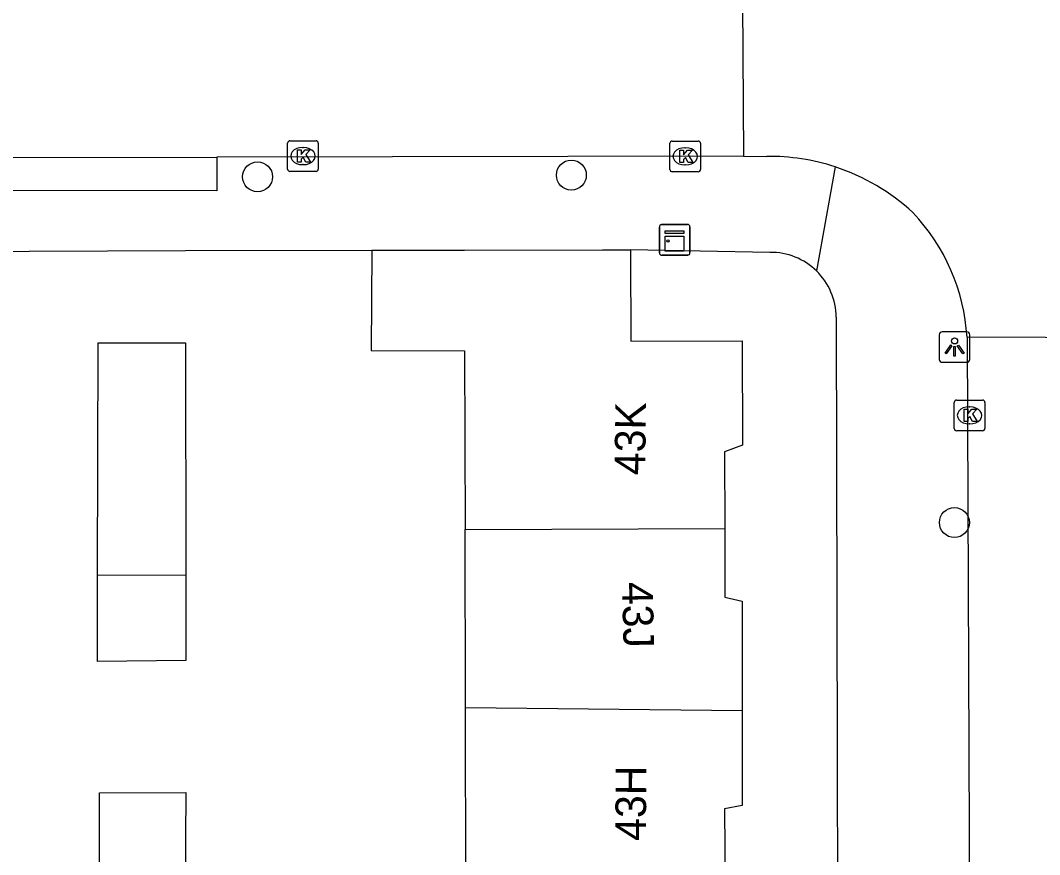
# Model space of a CAD drawing. Extents: x 160732 to 162105, y 387428 to 388479.
# Drawn here: x 161125.2 to 161158.48, y 388107.26 to 388134.52 of the extents above; entities that cross this region are included whole.
import ezdxf

# ---------------------------------------------------------------- set-up
doc = ezdxf.new("R2010")
doc.units = 0
for name, color, linetype in [('IMGEO_Boom', 7, 'Continuous'), ('IMGEO_Kast', 7, 'Continuous'), ('IMGEO_Kolk', 7, 'Continuous'), ('IMGEO_Lichtpunt', 7, 'Continuous'), ('IMGEO_Muur', 7, 'Continuous'), ('IMGEO_Pand', 7, 'Continuous'), ('IMGEO_Pand_nummerreeks', 7, 'Continuous'), ('IMGEO_Rijbaan_lokaal_open', 7, 'Continuous'), ('IMGEO_Voetpad_open', 7, 'Continuous')]:
    doc.layers.add(name, color=color, linetype=linetype)

msp = doc.modelspace()

# ---------------------------------------------------------------- linework, layer by layer
at = {"layer": 'IMGEO_Boom'}
for centre in [(161132.947, 388129.408), (161143.193, 388129.464), (161155.7, 388118.113)]:
    msp.add_circle(centre, 0.489, dxfattribs=at)
at = {"layer": 'IMGEO_Kast'}
for p, q in [((161146.067, 388126.924), (161146.067, 388127.765)), ((161146.067, 388127.765), (161146.067, 388126.924)), ((161146.142, 388127.849), (161146.983, 388127.849)), ((161146.983, 388127.849), (161146.142, 388127.849)), ((161147.067, 388127.774), (161147.067, 388126.933)), ((161147.067, 388126.933), (161147.067, 388127.774)), ((161146.992, 388126.849), (161146.151, 388126.849)), ((161146.151, 388126.849), (161146.992, 388126.849))]:
    msp.add_line(p, q, dxfattribs=at)
for points in [[(161146.262, 388127.639), (161146.862, 388127.639), (161146.862, 388127.554), (161146.262, 388127.554), (161146.262, 388127.639)], [(161146.262, 388127.464), (161146.862, 388127.464), (161146.862, 388126.975), (161146.262, 388126.975), (161146.262, 388127.464)]]:
    msp.add_lwpolyline(points, dxfattribs=at)
msp.add_circle((161146.346, 388127.313), 0.0377, dxfattribs=at)
for centre, start, end in [((161146.145, 388127.771), 92.4484, 184.2845), ((161146.145, 388127.771), 92.4484, 184.2845), ((161146.989, 388127.771), 2.4484, 94.2845), ((161146.989, 388127.771), 2.4484, 94.2845), ((161146.145, 388126.927), 182.4484, 274.2845), ((161146.145, 388126.927), 182.4484, 274.2845), ((161146.989, 388126.927), 272.4484, 4.2845), ((161146.989, 388126.927), 272.4484, 4.2845)]:
    msp.add_arc(centre, 0.0779, start, end, dxfattribs=at)
at = {"layer": 'IMGEO_Kolk'}
for p, q in [((161133.93, 388129.659), (161133.93, 388130.511)), ((161134.005, 388130.585), (161134.857, 388130.585)), ((161134.418, 388130.365), (161134.443, 388130.365)), ((161134.931, 388130.511), (161134.931, 388129.659)), ((161146.412, 388129.65), (161146.412, 388130.502)), ((161146.487, 388130.576), (161147.339, 388130.576)), ((161146.9, 388130.356), (161146.925, 388130.356)), ((161147.413, 388130.502), (161147.413, 388129.65)), ((161134.441, 388129.805), (161134.416, 388129.805)), ((161146.923, 388129.796), (161146.898, 388129.796)), ((161134.857, 388129.585), (161134.005, 388129.585)), ((161147.339, 388129.576), (161146.487, 388129.576)), ((161155.695, 388121.188), (161155.695, 388122.04)), ((161155.77, 388122.114), (161156.622, 388122.114)), ((161156.696, 388122.04), (161156.696, 388121.188)), ((161156.183, 388121.894), (161156.208, 388121.894)), ((161156.206, 388121.334), (161156.181, 388121.334)), ((161156.622, 388121.114), (161155.77, 388121.114))]:
    msp.add_line(p, q, dxfattribs=at)
for points in [[(161133.93, 388129.659), (161133.93, 388130.511)], [(161134.005, 388130.585), (161134.857, 388130.585)], [(161134.931, 388130.511), (161134.931, 388129.659)], [(161146.412, 388129.65), (161146.412, 388130.502)], [(161146.487, 388130.576), (161147.339, 388130.576)], [(161147.413, 388130.502), (161147.413, 388129.65)], [(161134.251, 388130.285), (161134.374, 388130.285), (161134.374, 388130.134), (161134.504, 388130.285), (161134.668, 388130.285), (161134.522, 388130.134), (161134.675, 388129.885), (161134.523, 388129.885), (161134.438, 388130.049), (161134.374, 388129.982), (161134.374, 388129.885), (161134.251, 388129.885), (161134.251, 388130.285)], [(161146.733, 388130.276), (161146.856, 388130.276), (161146.856, 388130.125), (161146.986, 388130.276), (161147.15, 388130.276), (161147.004, 388130.125), (161147.157, 388129.876), (161147.005, 388129.876), (161146.92, 388130.04), (161146.856, 388129.973), (161146.856, 388129.876), (161146.733, 388129.876), (161146.733, 388130.276)], [(161134.857, 388129.585), (161134.005, 388129.585)], [(161147.339, 388129.576), (161146.487, 388129.576)], [(161155.695, 388121.188), (161155.695, 388122.04)], [(161155.77, 388122.114), (161156.622, 388122.114)], [(161156.696, 388122.04), (161156.696, 388121.188)], [(161156.016, 388121.814), (161156.139, 388121.814), (161156.139, 388121.663), (161156.269, 388121.814), (161156.433, 388121.814), (161156.287, 388121.663), (161156.44, 388121.414), (161156.288, 388121.414), (161156.203, 388121.578), (161156.139, 388121.511), (161156.139, 388121.414), (161156.016, 388121.414), (161156.016, 388121.814)], [(161156.622, 388121.114), (161155.77, 388121.114)]]:
    msp.add_lwpolyline(points, dxfattribs=at)
for centre, start, end in [((161134.007, 388130.509), 91.552, 178.448), ((161134.007, 388130.509), 91.552, 178.448), ((161134.855, 388130.509), 1.552, 88.448), ((161134.855, 388130.509), 1.552, 88.448), ((161146.489, 388130.5), 91.552, 178.448), ((161146.489, 388130.5), 91.552, 178.448), ((161147.337, 388130.5), 1.552, 88.448), ((161147.337, 388130.5), 1.552, 88.448), ((161134.007, 388129.661), 181.552, 268.448), ((161134.007, 388129.661), 181.552, 268.448), ((161134.855, 388129.661), 271.552, 358.448), ((161134.855, 388129.661), 271.552, 358.448), ((161146.489, 388129.652), 181.552, 268.448), ((161146.489, 388129.652), 181.552, 268.448), ((161147.337, 388129.652), 271.552, 358.448), ((161147.337, 388129.652), 271.552, 358.448), ((161155.772, 388122.038), 91.552, 178.448), ((161155.772, 388122.038), 91.552, 178.448), ((161156.62, 388122.038), 1.552, 88.448), ((161156.62, 388122.038), 1.552, 88.448), ((161155.772, 388121.19), 181.552, 268.448), ((161155.772, 388121.19), 181.552, 268.448), ((161156.62, 388121.19), 271.552, 358.448), ((161156.62, 388121.19), 271.552, 358.448)]:
    msp.add_arc(centre, 0.0765, start, end, dxfattribs=at)
for centre, major_axis, ratio, start_param, end_param in [((161134.417, 388130.085), (-0.387, 0.002), 0.722429, 4.712389, 7.853982), ((161134.442, 388130.085), (-0.39, 0.002), 0.717154, 1.570796, 4.712389), ((161146.899, 388130.076), (-0.387, 0.002), 0.722429, 4.712389, 7.853982), ((161146.924, 388130.076), (-0.39, 0.002), 0.717154, 1.570796, 4.712389), ((161156.182, 388121.614), (-0.387, 0.002), 0.722429, 4.712389, 7.853982), ((161156.207, 388121.614), (-0.39, 0.002), 0.717154, 1.570796, 4.712389)]:
    msp.add_ellipse(centre, major_axis=major_axis, ratio=ratio, start_param=start_param, end_param=end_param, dxfattribs=at)
at = {"layer": 'IMGEO_Lichtpunt'}
for p, q in [((161156.11, 388124.345), (161155.302, 388124.345)), ((161156.11, 388124.345), (161155.302, 388124.345)), ((161155.208, 388124.25), (161155.208, 388123.443)), ((161155.208, 388124.25), (161155.208, 388123.443)), ((161156.204, 388123.443), (161156.204, 388124.25)), ((161156.204, 388123.443), (161156.204, 388124.25)), ((161155.302, 388123.349), (161156.11, 388123.349)), ((161155.302, 388123.349), (161156.11, 388123.349))]:
    msp.add_line(p, q, dxfattribs=at)
for points in [[(161155.582, 388123.914), (161155.621, 388123.886), (161155.433, 388123.624), (161155.395, 388123.651), (161155.582, 388123.914)], [(161155.684, 388123.866), (161155.731, 388123.866), (161155.731, 388123.544), (161155.684, 388123.544), (161155.684, 388123.866)], [(161155.794, 388123.886), (161155.832, 388123.913), (161156.019, 388123.651), (161155.98, 388123.623), (161155.794, 388123.886)]]:
    msp.add_lwpolyline(points, dxfattribs=at)
msp.add_circle((161155.707, 388124.048), 0.0994, dxfattribs=at)
for centre, start, end in [((161155.302, 388124.25), 90, 180), ((161155.302, 388124.25), 90, 180), ((161156.11, 388124.25), 0, 90), ((161156.11, 388124.25), 0, 90), ((161155.302, 388123.443), 180, 270), ((161155.302, 388123.443), 180, 270), ((161156.11, 388123.443), 270, 0), ((161156.11, 388123.443), 270, 360)]:
    msp.add_arc(centre, 0.0946, start, end, dxfattribs=at)
at = {"layer": 'IMGEO_Muur'}
msp.add_lwpolyline([(161130.593, 388126.998), (161139.701, 388127.012)], dxfattribs=at)
at = {"layer": 'IMGEO_Pand'}
for points in [[(161136.679, 388127.008), (161136.659, 388123.737), (161139.709, 388123.719), (161139.722, 388117.89)], [(161136.679, 388127.008), (161139.701, 388127.012), (161144.21, 388127.021), (161145.129, 388127.023)], [(161145.129, 388127.023), (161145.129, 388126.905), (161145.134, 388124.041), (161148.774, 388124.047), (161148.783, 388120.638), (161148.195, 388120.425), (161148.203, 388117.914)], [(161127.723, 388116.389), (161127.741, 388123.987), (161130.596, 388123.985), (161130.603, 388116.38)], [(161139.722, 388117.89), (161148.203, 388117.914)], [(161139.734, 388112.069), (161139.722, 388117.89)], [(161148.203, 388117.914), (161148.21, 388115.677), (161148.766, 388115.541), (161148.771, 388111.97)], [(161130.603, 388116.38), (161130.606, 388113.604), (161127.717, 388113.571), (161127.723, 388116.389)], [(161130.603, 388116.38), (161127.723, 388116.389)], [(161139.734, 388112.069), (161148.771, 388111.97)], [(161139.747, 388106.189), (161139.734, 388112.069)], [(161148.771, 388111.97), (161148.776, 388108.871), (161148.198, 388108.755), (161148.211, 388106.117)], [(161127.783, 388106.291), (161127.782, 388109.279), (161130.604, 388109.29), (161130.586, 388106.267)]]:
    msp.add_lwpolyline(points, dxfattribs=at)
at = {"layer": 'IMGEO_Rijbaan_lokaal_open'}
for points in [[(161148.781, 388135.121), (161148.814, 388130.087)], [(161122.435, 388130.036), (161131.623, 388130.048)], [(161148.814, 388130.087), (161131.623, 388130.048)], [(161148.814, 388130.087), (161149.577, 388130.075)], [(161156.115, 388124.167), (161156.36, 388064.733)], [(161161.231, 388124.147), (161156.115, 388124.167)]]:
    msp.add_lwpolyline(points, dxfattribs=at)
for centre, radius, start, end in [((161149.663, 388123.204), 6.872, 71.8332, 90.7208), ((161149.653, 388123.16), 6.917, 47.2746, 71.8653), ((161149.599, 388123.759), 6.528, 3.5839, 43.3587)]:
    msp.add_arc(centre, radius, start, end, dxfattribs=at)
at = {"layer": 'IMGEO_Voetpad_open'}
for points in [[(161131.623, 388130.048), (161131.616, 388128.954), (161122.469, 388128.958), (161122.435, 388130.036)], [(161151.806, 388129.733), (161151.2, 388126.332)], [(161099.983, 388126.872), (161130.593, 388126.998), (161136.679, 388127.008)], [(161149.679, 388126.939), (161145.129, 388127.023)], [(161151.839, 388124.823), (161151.979, 388062.934)]]:
    msp.add_lwpolyline(points, dxfattribs=at)
for centre, radius, start, end in [((161149.713, 388124.814), 2.125, 45.5842, 90.904), ((161149.718, 388124.815), 2.121, 0.2251, 45.6763)]:
    msp.add_arc(centre, radius, start, end, dxfattribs=at)

# ---------------------------------------------------------------- texts
at = {"layer": 'IMGEO_Pand_nummerreeks'}
for s, rotation, p in [('43K', 89.1522, (161145.599, 388119.658)), ('43J', 271.2416, (161144.85, 388116.163)), ('43H', 89.5062, (161145.625, 388107.713))]:
    msp.add_text(s, height=1, rotation=rotation, dxfattribs=at).set_placement(p)

doc.saveas('drawing.dxf')
